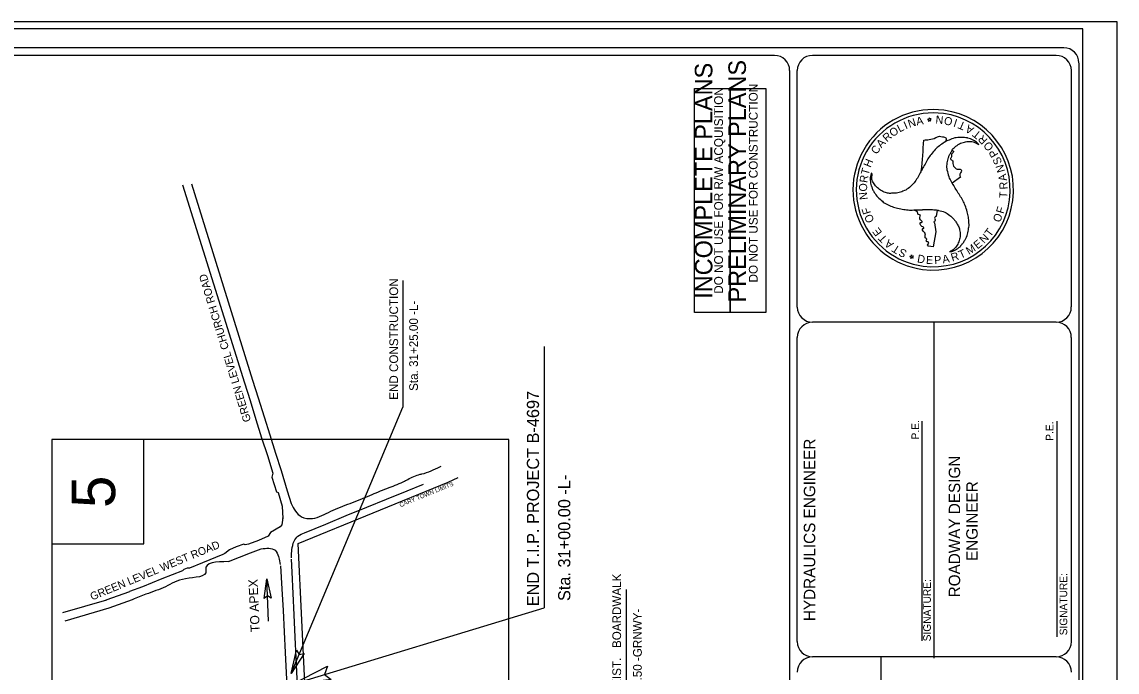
# Model space of a CAD drawing. Extents: x 2026893 to 2039781, y 729195 to 739590.
# Drawn here: x 2028226 to 2030743, y 738095 to 739590 of the extents above; entities that cross this region are included whole.
import ezdxf

# ---------------------------------------------------------------- set-up
doc = ezdxf.new("R2010")
doc.units = 0
for name, color, linetype in [('Default', 7, 'Continuous'), ('Old_Level_1', 7, 'Continuous'), ('Old_Level_2', 7, 'Continuous'), ('Old_Level_22', 7, 'Continuous'), ('Old_Level_3', 7, 'Continuous'), ('Prop Terminator CELL', 7, 'Continuous'), ('Sheet Cutting Line CELL', 7, 'Continuous'), ('Sheet Plot Border Inside CELL', 7, 'Continuous'), ('Sheet Plot Border Outside CELL', 7, 'Continuous'), ('Sheet Sticker Incomplete CELL', 7, 'Continuous'), ('Sheet Sticker Preliminary CELL', 7, 'Continuous'), ('Sheet Title CELL', 7, 'Continuous')]:
    doc.layers.add(name, color=color, linetype=linetype)

msp = doc.modelspace()

# ---------------------------------------------------------------- linework, layer by layer
at = {"layer": 'Default'}
for p, q in [((2028860.8, 738391.3), (2029205.1, 738532.1)), ((2028885.6, 737851.8), (2028860.8, 738391.3))]:
    msp.add_line(p, q, dxfattribs=at)
msp.add_lwpolyline([(2029205.1, 738532.1), (2029228.1, 738542.5)], dxfattribs=at)
at = {"layer": 'Old_Level_1'}
for p, q in [((2029101.4, 738995.2), (2029101.4, 738704.5)), ((2029426.2, 738843.7), (2029426.2, 738243.1)), ((2028844.6, 738092.3), (2029101.4, 738704.5)), ((2029615.3, 737932.6), (2029615.3, 738285.3)), ((2028845.7, 738067.3), (2029426.2, 738243.1))]:
    msp.add_line(p, q, dxfattribs=at)
at = {"layer": 'Old_Level_2'}
msp.add_line((2028792.4, 738212.6), (2028788.2, 738310), dxfattribs=at)
at = {"layer": 'Old_Level_22'}
for p, q in [((2028294.4, 738629.8), (2028294.4, 737129.7)), ((2029344.4, 738629.7), (2028294.4, 738629.8)), ((2028505.9, 738390.5), (2028505.9, 738629.8)), ((2029344.4, 737129.7), (2029344.4, 738629.7)), ((2028294.4, 738390.5), (2028505.9, 738390.5))]:
    msp.add_line(p, q, dxfattribs=at)
at = {"layer": 'Old_Level_3'}
for p, q in [((2028845.4, 738357.9), (2028845.4, 738360.3)), ((2028472.6, 738280.3), (2028418.8, 738260.7)), ((2028420.1, 738261), (2028318.9, 738231.4)), ((2028479.3, 738261.9), (2028425.6, 738242.2)), ((2028425.6, 738242.2), (2028324.4, 738212.6))]:
    msp.add_line(p, q, dxfattribs=at)
for points in [[(2028594.4, 739215.7), (2028737.2, 738760.5), (2028750, 738719.4), (2028763.4, 738676.3), (2028776.6, 738633.9), (2028789.7, 738593.1), (2028802, 738552.6), (2028800.3, 738543.7), (2028810.6, 738509.7), (2028814.5, 738508.5), (2028823.6, 738476.5), (2028825.4, 738448.5), (2028825.3, 738450.1), (2028823.1, 738434.1), (2028819, 738429.2), (2028796.8, 738416.1), (2028791.7, 738407.9), (2028769.6, 738398.3), (2028746.7, 738389.2), (2028738.7, 738388.3), (2028735.9, 738389.3), (2028718.1, 738383), (2028702.5, 738376.8), (2028692.2, 738367.9), (2028687.5, 738365.6), (2028640.5, 738346.5), (2028610.4, 738334.4), (2028605.6, 738334), (2028598, 738330.9), (2028594.3, 738328.1), (2028547.5, 738309.5), (2028502.7, 738291.7), (2028472.8, 738280.4)], [(2028615, 739217.6), (2028755.7, 738766.2), (2028768.3, 738726.2), (2028782.2, 738682), (2028795.3, 738641.1), (2028808.7, 738598.3), (2028821.1, 738558.9), (2028835.4, 738512), (2028844.3, 738483.3)], [(2029018.1, 738474.8), (2029063.3, 738493.1), (2029110.8, 738512.4), (2029148.7, 738527.5)], [(2028875.2, 738415.9), (2028923.9, 738435.8), (2028970.9, 738455.6)], [(2028970.9, 738455.6), (2029018.1, 738474.8)], [(2028700.3, 738349.4), (2028751.2, 738369.6), (2028775.7, 738378.7)], [(2028815.6, 738361), (2028817, 738354.9), (2028818.9, 738342.4)], [(2028891.4, 737417.9), (2028886.9, 737480.2), (2028883.8, 737534.3), (2028880.8, 737589.8), (2028877.9, 737642.4), (2028875.3, 737692.7), (2028873, 737740.5), (2028870.7, 737792.7), (2028868.6, 737841.5), (2028866.5, 737889.9), (2028862.6, 737982.7), (2028860.1, 738030.3), (2028858, 738079.6), (2028855.7, 738128.3), (2028853.7, 738176), (2028851, 738227.2), (2028849, 738276.4), (2028846.7, 738325.3), (2028845.4, 738355.3)], [(2028819.7, 738339.7), (2028823.3, 738286.5), (2028825.8, 738237.2), (2028828.4, 738187.7), (2028830.3, 738140.3), (2028833.4, 738078.8), (2028835.7, 738029.1), (2028837.3, 737981.2), (2028839.4, 737935.7), (2028841.2, 737889.8), (2028843.4, 737840.1), (2028845.7, 737790.9), (2028848.1, 737739.3), (2028851.5, 737682.8), (2028854.1, 737628.7), (2028856.9, 737578.1), (2028859.8, 737526), (2028862.4, 737478.4), (2028864.4, 737442.8), (2028866.7, 737411.7)]]:
    msp.add_lwpolyline(points, dxfattribs=at)
for points in [[(2028844.3, 738483.3), (2028868, 738452.5), (2028893.4, 738448.5), (2028935.4, 738465.2), (2028980, 738483.3), (2029025.4, 738501.7), (2029064.6, 738517.7), (2029102, 738532.8), (2029112.5, 738538.3), (2029141.1, 738550.1), (2029144.8, 738550.9), (2029186.4, 738567.5), (2029189.4, 738568.9)], [(2028845.4, 738360.3), (2028846.1, 738376.7), (2028851.3, 738396.1), (2028860.1, 738407.9), (2028875.2, 738415.9)], [(2028775.7, 738378.7), (2028793.1, 738380.1), (2028807.3, 738375.4), (2028815.6, 738361)], [(2028700.3, 738349.4), (2028648.1, 738330.3), (2028648.4, 738328.7), (2028601.7, 738310.1), (2028555.4, 738291.6), (2028510.6, 738274.3), (2028479.3, 738261.9)]]:
    msp.add_spline(points, degree=3, dxfattribs=at)
at = {"layer": 'Prop Terminator CELL'}
for points in [[(2028782.4, 738264.7), (2028788.2, 738310), (2028798.1, 738265.2), (2028789.9, 738270.6)], [(2028874, 738138.5), (2028844.6, 738092.3), (2028856.7, 738146), (2028862.9, 738136)], [(2028936.3, 738078.5), (2028845.7, 738067.3), (2028927.7, 738108.8), (2028921.3, 738090.2)]]:
    msp.add_lwpolyline(points, close=True, dxfattribs=at)
at = {"layer": 'Sheet Cutting Line CELL'}
msp.add_line((2030742.8, 733695.9), (2030742.8, 739589.9), dxfattribs=at)
at = {"layer": 'Sheet Plot Border Inside CELL'}
msp.add_lwpolyline([(2030664.3, 733741.4), (2030664.3, 739574.2), (2026971.4, 739574.2), (2026971.4, 733741.4)], close=True, dxfattribs=at)
at = {"layer": 'Sheet Plot Border Outside CELL'}
msp.add_lwpolyline([(2026892.9, 739589.9), (2026892.9, 733695.9), (2030742.8, 733695.9), (2030742.8, 739589.9)], close=True, dxfattribs=at)
at = {"layer": 'Sheet Sticker Incomplete CELL'}
msp.add_lwpolyline([(2029853.5, 738922.3), (2029771.3, 738922.3), (2029771.3, 739436.8), (2029853.5, 739436.8)], close=True, dxfattribs=at)
at = {"layer": 'Sheet Sticker Preliminary CELL'}
msp.add_lwpolyline([(2029935.8, 738922.3), (2029853.5, 738922.3), (2029853.5, 739436.8), (2029935.8, 739436.8)], close=True, dxfattribs=at)
at = {"layer": 'Sheet Title CELL'}
for p, q in [((2029990.3, 734507.9), (2029990.3, 739477.9)), ((2030007.8, 738934.6), (2030007.8, 739477.9)), ((2030344.5, 739386.9), (2030344.5, 739386.9)), ((2030310.4, 739366.5), (2030307.3, 739365.8)), ((2030307.3, 739365.8), (2030310.1, 739364.4)), ((2030310.1, 739364.4), (2030309.7, 739361.3)), ((2030309.7, 739361.3), (2030311.9, 739363.6)), ((2030310.7, 739369.6), (2030310.4, 739366.5)), ((2030312.3, 739366.8), (2030310.7, 739369.6)), ((2030311.9, 739363.6), (2030314.8, 739362.3)), ((2030315.5, 739367.3), (2030312.3, 739366.8)), ((2030313.3, 739365), (2030315.5, 739367.3)), ((2030314.8, 739362.3), (2030313.3, 739365)), ((2030177.9, 739242.7), (2030178.3, 739242.3)), ((2030177.9, 739242.7), (2030178.3, 739242.3)), ((2030292.9, 739247.3), (2030292.9, 739247.3)), ((2030382.6, 739232.7), (2030363.9, 739219.6)), ((2030363.9, 739219.6), (2030363.9, 739219.6)), ((2030329.4, 739157.5), (2030327.3, 739143)), ((2030326.2, 739107.3), (2030320.3, 739072.8)), ((2030323, 739128), (2030326.2, 739107.3)), ((2030320.3, 739072.8), (2030309.3, 739074.7)), ((2030266.4, 739050.5), (2030269.5, 739051.2)), ((2030269.2, 739049.2), (2030266.4, 739050.5)), ((2030268.8, 739046), (2030269.2, 739049.2)), ((2030271, 739048.3), (2030268.8, 739046)), ((2030269.5, 739051.2), (2030269.9, 739054.3)), ((2030269.9, 739054.3), (2030271.4, 739051.5)), ((2030273.9, 739047), (2030271, 739048.3)), ((2030271.4, 739051.5), (2030274.6, 739052)), ((2030274.6, 739052), (2030272.4, 739049.7)), ((2030272.4, 739049.7), (2030273.9, 739047)), ((2030602.8, 738899.6), (2030042.8, 738899.6)), ((2030322.7, 738127.3), (2030322.7, 738899.6)), ((2030007.8, 738165.4), (2030007.8, 738864.6)), ((2030294.8, 738167.2), (2030294.8, 738672)), ((2030604.7, 738176.8), (2030604.8, 738672.1)), ((2030602.9, 738130.4), (2030042.9, 738130.4)), ((2030199.5, 738130.4), (2030199.4, 737062.9))]:
    msp.add_line(p, q, dxfattribs=at)
for points in [[(2030620.3, 739530.4), (2027015.4, 739530.4)], [(2029955.4, 739512.9), (2027032.8, 739512.9)], [(2030602.8, 739512.9), (2030042.8, 739512.9)], [(2030655.4, 734315.4), (2030655.4, 739495.4)], [(2030637.8, 738934.7), (2030637.8, 739477.9)], [(2030637.8, 738165.4), (2030637.8, 738864.7)]]:
    msp.add_lwpolyline(points, dxfattribs=at)
for centre, radius, start, end in [((2029955.2, 739478), 35, 360, 90), ((2030042.7, 739478), 35, 90, 180), ((2030602.7, 739478), 35, 360, 90), ((2030620.2, 739495.5), 35, 360, 90), ((2030320.2, 739204), 184.5, 82.4211, 262.4211), ((2030320.2, 739204), 184.5, 262.4211, 82.4211), ((2030320.2, 739204), 176.8, 82.4211, 262.4211), ((2030320.2, 739204), 176.8, 262.4211, 82.4211), ((2029326.2, 739356.7), 972.8, 353.5387, 357.7447), ((2029326.2, 739356.7), 972.8, 348.0996, 348.1992), ((2030042.8, 738934.6), 35, 180, 270), ((2030602.6, 738934.7), 35, 270, 360), ((2030042.8, 738864.6), 35, 90, 180), ((2030602.6, 738864.7), 35, 360, 90), ((2030042.7, 738165.5), 35, 180, 270), ((2030602.7, 738165.5), 35, 270, 360), ((2030042.7, 738095.5), 35, 90, 180), ((2030602.7, 738095.5), 35, 360, 90)]:
    msp.add_arc(centre, radius, start, end, dxfattribs=at)
for points in [[(2030424.7, 739308), (2030422.2, 739311.2), (2030412.2, 739318.4), (2030399.9, 739322.9), (2030398.6, 739323.2), (2030391.7, 739324.2), (2030383.3, 739324.4), (2030369.7, 739323.1), (2030356.6, 739318.4), (2030351.1, 739316.4), (2030345.5, 739312.9), (2030334.3, 739305.1), (2030325, 739296.5), (2030315.4, 739285.3), (2030307.8, 739274.9), (2030301.3, 739263.1), (2030295, 739251.2), (2030288.7, 739239.9), (2030282, 739228.1), (2030274, 739217.7), (2030273.2, 739216.9), (2030262.7, 739207), (2030250.7, 739200.8), (2030238.7, 739197), (2030232.4, 739196.1), (2030224.5, 739196), (2030220, 739195.8), (2030210.8, 739197.7), (2030198.9, 739203), (2030189.7, 739211), (2030182.8, 739220), (2030178.9, 739230.8), (2030178.3, 739242.3), (2030177.9, 739242.7)], [(2030348.9, 739315.4), (2030345.5, 739312.9), (2030334.3, 739305.1), (2030325, 739296.5), (2030315.4, 739285.3), (2030307.8, 739274.9), (2030301.3, 739263.1), (2030295, 739251.2), (2030292.9, 739247.3)], [(2030298.3, 739318.4), (2030310.8, 739319.4), (2030326.1, 739323.9), (2030334.5, 739327), (2030341.2, 739326), (2030349.1, 739323.3), (2030348.9, 739315.4)], [(2030358.4, 739061.6), (2030362.7, 739062.3), (2030373.8, 739067.4), (2030383.9, 739075.8), (2030384.5, 739076.7), (2030389.2, 739082.3), (2030393.3, 739089.3), (2030399.1, 739101.9), (2030401.6, 739115.5), (2030402.6, 739121.2), (2030402.3, 739128.1), (2030401.1, 739141.4), (2030398.4, 739153.7), (2030393.5, 739167.8), (2030388.3, 739179.5), (2030381.3, 739191), (2030374.1, 739202.3), (2030367.4, 739213.6), (2030360.8, 739225.2), (2030355.6, 739237.3), (2030355.3, 739238.6), (2030352, 739252.5), (2030352.6, 739265.9), (2030355.3, 739278.1), (2030357.6, 739284.4), (2030361.6, 739291), (2030363.6, 739295.2), (2030369.8, 739302.1), (2030380.3, 739309.6), (2030391.9, 739313.7), (2030403.2, 739315.3), (2030414.5, 739313.3), (2030424.7, 739308)], [(2030363.9, 739219.6), (2030360.8, 739225.2), (2030355.6, 739237.3), (2030355.3, 739238.6), (2030352, 739252.5), (2030352.6, 739265.9), (2030355.3, 739278.1), (2030357.6, 739284.4), (2030361.6, 739291), (2030363.5, 739294.9)], [(2030363.6, 739294.8), (2030366.5, 739292.7), (2030366.4, 739289.9), (2030361.9, 739285.6), (2030362.3, 739279.5), (2030360.4, 739277), (2030360.1, 739275.2), (2030364.9, 739270.3), (2030365.4, 739264.2), (2030371.1, 739253.8), (2030374.9, 739251.3), (2030383.8, 739250.9), (2030385.2, 739248.3), (2030384.4, 739245.5), (2030381.4, 739240), (2030382.6, 739232.7)], [(2030178.3, 739242.3), (2030176.6, 739238.3), (2030175.5, 739226.1), (2030177.8, 739213.2), (2030178.3, 739212), (2030180.7, 739205.4), (2030184.7, 739198.2), (2030192.8, 739187.1), (2030203.3, 739177.9), (2030207.8, 739174.2), (2030213.6, 739171.2), (2030226, 739165.4), (2030238.2, 739161.7), (2030252.6, 739158.9), (2030265.5, 739157.4), (2030278.8, 739157.8), (2030292.3, 739158.3), (2030305.3, 739158.5), (2030318.7, 739158.5), (2030331.8, 739156.9), (2030332.9, 739156.7), (2030346.6, 739152.5), (2030358, 739145.2), (2030367.3, 739136.6), (2030371.4, 739131.7), (2030375.4, 739124.9), (2030377.7, 739121.1), (2030380.8, 739112.2), (2030382.1, 739099.3), (2030379.7, 739087.2), (2030375.5, 739076.7), (2030368.1, 739068), (2030358.4, 739061.6)], [(2030278.5, 739157.8), (2030278.8, 739157.8), (2030292.3, 739158.3), (2030305.3, 739158.5), (2030318.7, 739158.5), (2030329.4, 739157.4)], [(2030309.3, 739074.7), (2030308.3, 739074.4), (2030307.3, 739076.4), (2030310.1, 739081.3), (2030308.2, 739084.2), (2030306, 739084.4), (2030304.1, 739086.7), (2030305.2, 739090.2), (2030301.6, 739093.9), (2030301.3, 739096.9), (2030302.1, 739103.1), (2030295.7, 739111.4), (2030295.7, 739114.6), (2030297.7, 739115.1), (2030298.4, 739116.9), (2030292.7, 739120.9), (2030291.9, 739121.8), (2030290.4, 739127.8), (2030291.7, 739129.2), (2030294.5, 739129.3), (2030295.1, 739130), (2030294, 739132.1), (2030291.1, 739135.1), (2030289.3, 739140.1), (2030290.7, 739145.4), (2030286.4, 739146.9), (2030283, 739153.8), (2030280.6, 739155.4), (2030278.1, 739156.1)], [(2030327.3, 739143), (2030324.5, 739142), (2030323.3, 739139.2), (2030324.8, 739135.2), (2030324.2, 739132.3), (2030321.5, 739129.5), (2030323, 739128)]]:
    msp.add_spline(points, degree=3, dxfattribs=at)

# ---------------------------------------------------------------- texts
at = {"layer": 'Default'}
msp.add_text('CARY TOWN LIMITS', height=10, rotation=22.2389, dxfattribs=at).set_placement((2029095.8, 738474.3))
at = {"layer": 'Old_Level_1'}
for s, height, p in [('END CONSTRUCTION', 20, (2029090.2, 738721.3)), ('Sta. 31+25.00 -L-', 20, (2029135.8, 738741.8)), ('END T.I.P. PROJECT B-4697', 28, (2029414.2, 738246.6)), ('Sta. 31+00.00 -L-', 28, (2029486.1, 738258.8)), ('TIE TO EXIST.   BOARDWALK', 20, (2029602.7, 737950.2)), ('Sta. 11+78.50 -GRNWY-', 20, (2029650.3, 737946.1))]:
    msp.add_text(s, height=height, rotation=90, dxfattribs=at).set_placement(p)
at = {"layer": 'Old_Level_2'}
for s, height, rotation, p in [('GREEN LEVEL CHURCH ROAD', 18, 106.935, (2028752.5, 738673.3)), ('GREEN LEVEL WEST ROAD', 18, 22.4315, (2028386.8, 738259.8)), ('TO APEX', 21, 92.4896, (2028772.4, 738187.8))]:
    msp.add_text(s, height=height, rotation=rotation, dxfattribs=at).set_placement(p)
at = {"layer": 'Old_Level_22'}
msp.add_text('5', height=100, rotation=90, dxfattribs=at).set_placement((2028439.9, 738472.7))
at = {"layer": 'Sheet Sticker Incomplete CELL'}
for s, height, p in [('INCOMPLETE PLANS', 40.32, (2029812.6, 738953.6)), ('DO NOT USE FOR R/W ACQUISITION', 20.16, (2029836.9, 738965))]:
    msp.add_text(s, height=height, rotation=90, dxfattribs=at).set_placement(p)
at = {"layer": 'Sheet Sticker Preliminary CELL'}
for s, height, p in [('PRELIMINARY PLANS', 40.32, (2029889.7, 738945.1)), ('DO NOT USE FOR CONSTRUCTION', 20.16, (2029916.7, 738990.9))]:
    msp.add_text(s, height=height, rotation=90, dxfattribs=at).set_placement(p)
at = {"layer": 'Sheet Title CELL'}
for s, height, rotation, p in [('I', 18.4, 24.0166, (2030257.2, 739342.8)), ('N', 18.4, 18.3165, (2030265.5, 739346.3)), ('A', 18.4, 10.8845, (2030282.7, 739351.9)), ('N', 18.4, 174.6293, (2030344.3, 739373.4)), ('O', 18.3, 167.3812, (2030366, 739368.7)), ('I', 18.4, 162.2456, (2030377.3, 739365.3)), ('T', 18.4, 156.5957, (2030396.4, 739357.1)), ('R', 18.4, 41.3592, (2030213.6, 739313)), ('O', 18.4, 34.2396, (2030226.9, 739324.6)), ('L', 18.3, 28.0059, (2030243, 739335.6)), ('A', 18.4, 149.5113, (2030415.3, 739346.2)), ('T', 18.3, 141.4242, (2030431.8, 739333.5)), ('A', 18.4, 47.7231, (2030200.9, 739299)), ('R', 18.4, 135.3245, (2030446.5, 739319.4)), ('O', 18.4, 128.1354, (2030460.4, 739302)), ('C', 18.3, 55.2202, (2030190.4, 739284)), ('P', 18.4, 121.4434, (2030470.8, 739285.2)), ('H', 18.4, 67.5625, (2030176.1, 739253.9)), ('S', 18.3, 114.2515, (2030479.2, 739266.7)), ('N', 18.3, 107.041, (2030485.7, 739246.9)), ('R', 18.4, 81.2969, (2030168.6, 739219.1)), ('T', 18.4, 74.6472, (2030171.2, 739236.5)), ('A', 18.3, 100.0094, (2030489.8, 739225.6)), ('O', 18.4, 87.9068, (2030167.9, 739199.7)), ('R', 18.4, 93.2563, (2030491.2, 739205.3)), ('N', 18.4, 95.4049, (2030169.5, 739181.8)), ('T', 18.3, 86.2997, (2030490.1, 739184.5)), ('F', 18.4, 107.4918, (2030177.4, 739150.8)), ('F', 18.4, 73.3904, (2030481.7, 739147.8)), ('O', 18.4, 114.6387, (2030185.4, 739133)), ('O', 18.4, 66.2252, (2030473, 739127.4)), ('E', 18.3, 126.5781, (2030203.5, 739105.9)), ('T', 18.4, 52.9215, (2030451.5, 739094.5)), ('T', 18.4, 133.6937, (2030215.9, 739092.8)), ('A', 18.5, 140.7489, (2030230.7, 739080.8)), ('E', 18.3, 39.108, (2030422, 739066.7)), ('N', 18.4, 46.0795, (2030437.3, 739079.4)), ('T', 18.4, 147.8012, (2030245.7, 739071)), ('S', 18.4, 154.1774, (2030261.5, 739063.3)), ('R', 18.4, 17.7556, (2030364.1, 739038.9)), ('T', 18.4, 24.4062, (2030383.4, 739045.2)), ('M', 18.3, 31.6412, (2030402.3, 739054.1)), ('D', 18.4, 350.2741, (2030282.3, 739037.4)), ('E', 18.3, 356.562, (2030303.2, 739034)), ('P', 18.4, 4.0944, (2030323.1, 739033.2)), ('A', 18.4, 10.687, (2030342.7, 739034.6)), ('P.E.', 17.5, 90, (2030287.6, 738630.2)), ('P.E.', 17.5, 90, (2030596.3, 738627.1)), (' HYDRAULICS ENGINEER', 26.25, 90, (2030049, 738202.9)), ('ROADWAY DESIGN', 26.248, 90, (2030382.1, 738267.3)), ('ENGINEER', 26.25, 90, (2030422.4, 738350.8)), ('SIGNATURE:', 17.5, 90, (2030314.7, 738166.2)), ('SIGNATURE:', 17.5, 90, (2030628.2, 738180))]:
    msp.add_text(s, height=height, rotation=rotation, dxfattribs=at).set_placement(p)

doc.saveas('drawing.dxf')
